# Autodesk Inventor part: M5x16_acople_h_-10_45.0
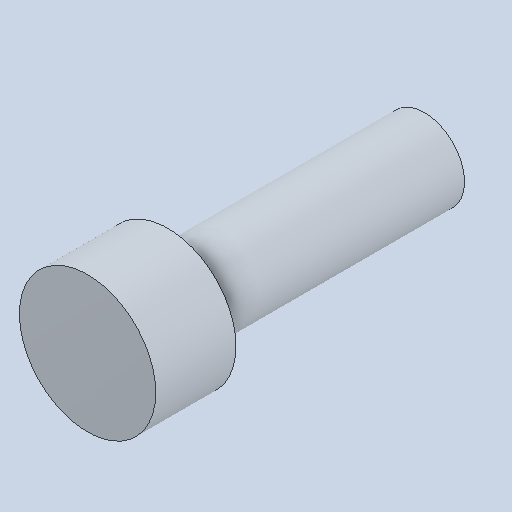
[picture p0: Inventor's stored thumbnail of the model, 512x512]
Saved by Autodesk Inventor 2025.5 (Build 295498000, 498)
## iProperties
Created: 2026-10
Part Number: M5x16_acople_h_-10_45.0
Material: Genérico
Document SubType Name: Modeling
Designer: Luis M
Density: 1 g/cm^3
Appearance: Valor por defecto
Author: Luis M
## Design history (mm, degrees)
feature "Base1"
node "Sólido1"
